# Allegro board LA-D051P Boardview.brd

Outline 214.4 x 122.8 mm; copper layers: TOP, GND1, IN1, VCC, IN2, IN3, GND2, BOTTOM. Coordinates in mm from the lower left corner of the outline.

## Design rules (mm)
constraint set DEFAULT: min track width 0.102
net group CLK_SMB: nets CLK_SMB DAT_SMB
net group DIFFPAIR0: nets A_MIC_CLK A_MIC_DATA
net group DIFFPAIR3: nets CLK_CPU_ITP CLK_CPU_ITP#
net group DIFFPAIR35: nets ICSP_CLK ICSP_DAT
net group DIFFPAIR36: nets MSCLK MSDATA
net group DIFFPAIR48: nets PEX_PLL_CLK_OUT PEX_PLL_CLK_OUT#
net group DIFFPAIR84: nets USB3_CTX_C_DRX_N3 USB3_CTX_C_DRX_P3
net group DIFFPAIR96: nets VCC_GT_SENSE VSS_GT_SENSE
net group PECI: nets PECI_EC PECI_MEC1404
net group SVID: nets VIDALERT_N VIDSOUT
net group W12S12: nets PCIE_RCOMPN PCIE_RCOMPP
net group W12S15: nets SD_RCOMP XCLK_BIASREF
net group 15: nets EC_SPI_CLK EC_SPICLK_R EMMC_RCOMP GPU_BUFRST GPU_JTAG_TRST# GPU_THM_SMBCLK H_CPU_SVIDALRT# HDA_BIT_CLK HDA_CODEC_BITCLK HDA_CODEC_RST# HDA_RST# MEC_XTAL2 NVVDD_GND_SENSE NVVDD_SENSE PCH_PLTRST# PCH_RSMRST# PCH_RTCRST# PCH_RTCX1 PCH_RTCX2 PCH_SMBCLK PCH_SPI_CLK PCH_SPI_CLK_R PLT_RST_VGA# PLT_RST_VGA_MON# RTCRST_ON SMBCLK SML0_SMBCLK SRTCRST# SUSACK# TS_RST# USB2_COMP VCCSENSE VIDSCLK VR_SCLK VR_SDA VSA_SEN+ VSA_SEN- VSSSENSE XTAL24_IN XTAL24_OUT
net group ASYNCHRONOUS SIGNALS: nets H_THERMTRIP#
net group CLK: nets H_PROCHOT#
net group CPU: nets H_CATERR# H_PROCHOT#_R XDP_OBS0_R XDP_OBS1_R
net group CRITICAL: nets H_CPUPWRGD INTRUDER# PCH_DPWROK SYS_PWROK
net group DDR-DQS: nets DDR_A_DQS0 DDR_A_DQS1 DDR_A_DQS2 DDR_A_DQS3 DDR_A_DQS4 DDR_A_DQS5 DDR_A_DQS6 DDR_A_DQS7 DDR_A_DQS#0 DDR_A_DQS#1 DDR_A_DQS#2 DDR_A_DQS#3 DDR_A_DQS#4 DDR_A_DQS#5 DDR_A_DQS#6 DDR_A_DQS#7 DDR_B_DQS0 DDR_B_DQS1 DDR_B_DQS2 DDR_B_DQS3 DDR_B_DQS4 DDR_B_DQS5 DDR_B_DQS6 DDR_B_DQS7 DDR_B_DQS#0 DDR_B_DQS#1 DDR_B_DQS#2 DDR_B_DQS#3 DDR_B_DQS#4 DDR_B_DQS#5 DDR_B_DQS#6 DDR_B_DQS#7
net group DDR-RST: nets DDR_DRAMRST#
net group DDRA-CLK: nets DDR_A_CLK0 DDR_A_CLK1 DDR_A_CLK#0 DDR_A_CLK#1
net group DDRA-CMD: nets DDR_A_BS0 DDR_A_BS1 DDR_A_BS2 DDR_A_CAS# DDR_A_MA0 DDR_A_MA1 DDR_A_MA2 DDR_A_MA3 DDR_A_MA4 DDR_A_MA5 DDR_A_MA6 DDR_A_MA7 DDR_A_MA8 DDR_A_MA9 DDR_A_MA10 DDR_A_MA11 DDR_A_MA12 DDR_A_MA13 DDR_A_MA14 DDR_A_MA15 DDR_A_RAS# DDR_A_WE#
net group DDRA-CTL: nets DDR_A_CKE0 DDR_A_CKE1 DDR_A_CS#0 DDR_A_CS#1 DDR_A_ODT0 DDR_A_ODT1
net group DDRA-D0: nets DDR_A_D0 DDR_A_D1 DDR_A_D2 DDR_A_D3 DDR_A_D4 DDR_A_D5 DDR_A_D6 DDR_A_D7
net group DDRA-D1: nets DDR_A_D8 DDR_A_D9 DDR_A_D10 DDR_A_D11 DDR_A_D12 DDR_A_D13 DDR_A_D14 DDR_A_D15
net group DDRA-D2: nets DDR_A_D16 DDR_A_D17 DDR_A_D18 DDR_A_D19 DDR_A_D20 DDR_A_D21 DDR_A_D22 DDR_A_D23
net group DDRA-D3: nets DDR_A_D24 DDR_A_D25 DDR_A_D26 DDR_A_D27 DDR_A_D28 DDR_A_D29 DDR_A_D30 DDR_A_D31
net group DDRA-D4: nets DDR_A_D32 DDR_A_D33 DDR_A_D34 DDR_A_D35 DDR_A_D36 DDR_A_D37 DDR_A_D38 DDR_A_D39
net group DDRA-D5: nets DDR_A_D40 DDR_A_D41 DDR_A_D42 DDR_A_D43 DDR_A_D44 DDR_A_D45 DDR_A_D46 DDR_A_D47
net group DDRA-D6: nets DDR_A_D48 DDR_A_D49 DDR_A_D50 DDR_A_D51 DDR_A_D52 DDR_A_D53 DDR_A_D54 DDR_A_D55
net group DDRA-D7: nets DDR_A_D56 DDR_A_D57 DDR_A_D58 DDR_A_D59 DDR_A_D60 DDR_A_D61 DDR_A_D62 DDR_A_D63
net group DDRB-CLK: nets DDR_B_CLK0 DDR_B_CLK1 DDR_B_CLK#0 DDR_B_CLK#1
net group DDRB-CMD: nets DDR_B_BS0 DDR_B_BS1 DDR_B_BS2 DDR_B_CAS# DDR_B_MA0 DDR_B_MA1 DDR_B_MA2 DDR_B_MA3 DDR_B_MA4 DDR_B_MA5 DDR_B_MA6 DDR_B_MA7 DDR_B_MA8 DDR_B_MA9 DDR_B_MA10 DDR_B_MA11 DDR_B_MA12 DDR_B_MA13 DDR_B_MA14 DDR_B_MA15 DDR_B_RAS# DDR_B_WE#
net group DDRB-CTL: nets DDR_B_CKE0 DDR_B_CKE1 DDR_B_CS#0 DDR_B_CS#1 DDR_B_ODT0 DDR_B_ODT1
net group DDRB-D0: nets DDR_B_D0 DDR_B_D1 DDR_B_D2 DDR_B_D3 DDR_B_D4 DDR_B_D5 DDR_B_D6 DDR_B_D7
net group DDRB-D1: nets DDR_B_D8 DDR_B_D9 DDR_B_D10 DDR_B_D11 DDR_B_D12 DDR_B_D13 DDR_B_D14 DDR_B_D15
net group DDRB-D2: nets DDR_B_D16 DDR_B_D17 DDR_B_D18 DDR_B_D19 DDR_B_D20 DDR_B_D21 DDR_B_D22 DDR_B_D23
net group DDRB-D3: nets DDR_B_D24 DDR_B_D25 DDR_B_D26 DDR_B_D27 DDR_B_D28 DDR_B_D29 DDR_B_D30 DDR_B_D31
net group DDRB-D4: nets DDR_B_D32 DDR_B_D33 DDR_B_D34 DDR_B_D35 DDR_B_D36 DDR_B_D37 DDR_B_D38 DDR_B_D39
net group DDRB-D5: nets DDR_B_D40 DDR_B_D41 DDR_B_D42 DDR_B_D43 DDR_B_D44 DDR_B_D45 DDR_B_D46 DDR_B_D47
net group DDRB-D6: nets DDR_B_D48 DDR_B_D49 DDR_B_D50 DDR_B_D51 DDR_B_D52 DDR_B_D53 DDR_B_D54 DDR_B_D55
net group DDRB-D7: nets DDR_B_D56 DDR_B_D57 DDR_B_D58 DDR_B_D59 DDR_B_D60 DDR_B_D61 DDR_B_D62 DDR_B_D63
net group EDP: nets EDP_AUX#_C EDP_AUX_C EDP_AUX_DN EDP_AUX_DP EDP_TX0#_C EDP_TX0_C EDP_TX0_DN EDP_TX0_DP EDP_TX1#_C EDP_TX1_C EDP_TX1_DN EDP_TX1_DP
net group FBA-CLK: nets FB_A_CLK0 FB_A_CLK1 FB_A_CLK#0 FB_A_CLK#1
net group FBA-CMD: nets FB_A_CMD0 FB_A_CMD1 FB_A_CMD2 FB_A_CMD3 FB_A_CMD4 FB_A_CMD5 FB_A_CMD6 FB_A_CMD7 FB_A_CMD8 FB_A_CMD9 FB_A_CMD10 FB_A_CMD11 FB_A_CMD12 FB_A_CMD13 FB_A_CMD14 FB_A_CMD15 FB_A_CMD16 FB_A_CMD17 FB_A_CMD18 FB_A_CMD19 FB_A_CMD20 FB_A_CMD21 FB_A_CMD22 FB_A_CMD23 FB_A_CMD24 FB_A_CMD25 FB_A_CMD26 FB_A_CMD27 FB_A_CMD28 FB_A_CMD29 FB_A_CMD30
net group FBA-D0: nets FB_A_D0 FB_A_D1 FB_A_D2 FB_A_D3 FB_A_D4 FB_A_D5 FB_A_D6 FB_A_D7 FB_A_DQM0
net group FBA-D1: nets FB_A_D8 FB_A_D9 FB_A_D10 FB_A_D11 FB_A_D12 FB_A_D13 FB_A_D14 FB_A_D15 FB_A_DQM1
net group FBA-D2: nets FB_A_D16 FB_A_D17 FB_A_D18 FB_A_D19 FB_A_D20 FB_A_D21 FB_A_D22 FB_A_D23 FB_A_DQM2
net group FBA-D3: nets FB_A_D24 FB_A_D25 FB_A_D26 FB_A_D27 FB_A_D28 FB_A_D29 FB_A_D30 FB_A_D31 FB_A_DQM3
net group FBA-D4: nets FB_A_D32 FB_A_D33 FB_A_D34 FB_A_D35 FB_A_D36 FB_A_D37 FB_A_D38 FB_A_D39 FB_A_DQM4
net group FBA-D5: nets FB_A_D40 FB_A_D41 FB_A_D42 FB_A_D43 FB_A_D44 FB_A_D45 FB_A_D46 FB_A_D47 FB_A_DQM5
net group FBA-D6: nets FB_A_D48 FB_A_D49 FB_A_D50 FB_A_D51 FB_A_D52 FB_A_D53 FB_A_D54 FB_A_D55 FB_A_DQM6
net group FBA-D7: nets FB_A_D56 FB_A_D57 FB_A_D58 FB_A_D59 FB_A_D60 FB_A_D61 FB_A_D62 FB_A_D63 FB_A_DQM7
net group FBA-DQS: nets FB_A_DQS0 FB_A_DQS1 FB_A_DQS2 FB_A_DQS3 FB_A_DQS4 FB_A_DQS5 FB_A_DQS6 FB_A_DQS7 FB_A_DQS#0 FB_A_DQS#1 FB_A_DQS#2 FB_A_DQS#3 FB_A_DQS#4 FB_A_DQS#5 FB_A_DQS#6 FB_A_DQS#7
net group HDA: nets HDA_CODEC_SDIN0 HDA_CODEC_SDOUT HDA_CODEC_SYNC HDA_SDIN0 HDA_SDOUT HDA_SYNC
net group HDMI: nets CPU_DPB_CTRLCLK_R CPU_DPB_CTRLDAT_R HDMI_CLK HDMI_CLK# HDMI_DATA0 HDMI_DATA0# HDMI_DATA1 HDMI_DATA1# HDMI_DATA2 HDMI_DATA2# PCH_HDMI_CLK PCH_HDMI_DATA TMDS_L_TX0N TMDS_L_TX0P TMDS_L_TX1N TMDS_L_TX1P TMDS_L_TX2N TMDS_L_TX2P TMDS_L_TXCN TMDS_L_TXCP TMDS_TX0N TMDS_TX0P TMDS_TX1N TMDS_TX1P TMDS_TX2N TMDS_TX2P TMDS_TXCN TMDS_TXCP
net group HP: nets AUD_HP_OUT_L_CN AUD_HP_OUT_R_CN LINE-IN-L LINE-IN-R
net group I2C: nets I2C_SCL_TP I2C_SCL_TP_R I2C_SDA_TP I2C_SDA_TP_R I2CA_SCL I2CA_SDA I2CB_SCL I2CB_SDA I2CC_SCL I2CC_SDA I2CS_SCL I2CS_SDA
net group MDI: nets MDI0+ MDI0- MDI1+ MDI1- MDO0+ MDO0- MDO1+ MDO1-
net group PCIE: nets PCIE_PRX_LANTX_N3_C PCIE_PRX_LANTX_N6 PCIE_PRX_LANTX_P3_C PCIE_PRX_LANTX_P6 PCIE_PRX_WLANTX_N5 PCIE_PRX_WLANTX_P5 PCIE_PTX_LANRX_N6 PCIE_PTX_LANRX_N6_C PCIE_PTX_LANRX_P6 PCIE_PTX_LANRX_P6_C PCIE_PTX_WLANRX_N5 PCIE_PTX_WLANRX_N5_C PCIE_PTX_WLANRX_P5 PCIE_PTX_WLANRX_P5_C
net group PEG-RX_15_20/15/20/20/20: nets PCIE_CRX_C_GTX_N1 PCIE_CRX_C_GTX_N2 PCIE_CRX_C_GTX_N3 PCIE_CRX_C_GTX_N4 PCIE_CRX_C_GTX_P1 PCIE_CRX_C_GTX_P2 PCIE_CRX_C_GTX_P3 PCIE_CRX_C_GTX_P4 PCIE_CRX_GTX_N1 PCIE_CRX_GTX_N2 PCIE_CRX_GTX_N3 PCIE_CRX_GTX_N4 PCIE_CRX_GTX_P1 PCIE_CRX_GTX_P2 PCIE_CRX_GTX_P3 PCIE_CRX_GTX_P4
net group PEG-TX_15_20/15/20/20/20: nets PCIE_CTX_C_GRX_N1 PCIE_CTX_C_GRX_N2 PCIE_CTX_C_GRX_N3 PCIE_CTX_C_GRX_N4 PCIE_CTX_C_GRX_P1 PCIE_CTX_C_GRX_P2 PCIE_CTX_C_GRX_P3 PCIE_CTX_C_GRX_P4 PCIE_CTX_GRX_N1 PCIE_CTX_GRX_N2 PCIE_CTX_GRX_N3 PCIE_CTX_GRX_N4 PCIE_CTX_GRX_P1 PCIE_CTX_GRX_P2 PCIE_CTX_GRX_P3 PCIE_CTX_GRX_P4
net group PLATFORM CLK: nets CLK_PCIE_LAN_N2 CLK_PCIE_LAN_P2 CLK_PCIE_WLAN_N1 CLK_PCIE_WLAN_P1 CLK_PEG_VGA CLK_PEG_VGA#
net group POWER: nets +0.675VS_VREF_CA0 +0.675VS_VREF_CA1 +0.675VS_VREF_DQ0 +0.675VS_VREF_DQ1 +0.675VS_VTT +0.675VSP +1.0V_APLL +1.0V_CLK4_F100OC +1.0V_CLK5 +1.0V_CLK6_24TBT +1.0V_DTS +1.0V_MPHYJP +1.0V_MPHYPLL +1.0V_PRIM_D +1.0V_PRIM_JP +1.0V_VCCSFR +1.0V_VCCST +1.0V_VCCSTU +1.0V_XDP +1.0VO_DSW +1.0VS_DGPU +1.0VS_PLLAVDD +1.0VS_VCCSTG +1.0VS_VCCSTG_IO +1.8V_PRIM +1.8V_PRIM_VS +1.8VALWP +1.8VS +1.8VS_3VS_PGPPA +1.35V_VCCSFR_OC +1.35V_VDDQ +1.35V_VDDQC +1.35VP +1.35VS_VRAM +1VALWP +3V_1.8V_PGPPA +3V_PGPPB +3V_PGPPC +3V_PGPPE +3V_PRIM +3V_PRIM_RTC +3V_PRIMJP +3V_SPI +3VALW_DSW +3VALW_EC +3VALWP +3VL_RTC +3VLP +3VS_CAM +3VS_D +3VS_DGPU +3VS_DGPU_AON +3VS_TOUCH +5V_CAM +5V_HDD +5V_PVDD +5V_USB_PWR1 +5V_USB_PWR2 +5V_USB_PWR3 +5VA +5VALWP +5VS_KBL +17.4V_BATT+ +17.4V_BATT++ +19V_ADPIN +19V_VIN +19VB_1.35V +19VB_+1VALWP +19VB_VGA +A_VCC +CODEC_AVDD2 +FAN_POWER +LAN_REGOUT +LAN_VDD10 +LAN_VDD33 +LAN_VDDREG +LCDVDD +LCDVDD_CONN +MIC2-VREFO +RTCBATT +V_TS +VDD_TOUCH +VDISPLAY_VCC
net group REF-GND: nets ALL_SYS_PWRGD BLUETOOTH_EN BST1_VGA BST1_VGA_R BST2_VGA BST2_VGA_R BST_1.35V BST_1.35V_R BST_3V BST_5V CFG0 CFG1 CFG2 CFG3 CFG4 CFG5 CFG6 CFG7 CFG8 CFG9 CFG10 CFG11 CFG12 CFG13 CFG14 CFG15 CFG16 CFG17 CFG18 CFG19 CLK_PCI_LPC_MEC CPU_XDP_TCK0 LG1_VGA LG2_VGA LG_1.35V LGATE_CHG LPC_LAD0 LPC_LAD1 LPC_LAD2 LPC_LAD3 LX1_VGA LX2_VGA LX_1.8VALW LX_1.35V LX_3V LX_5V MIC_CLK_C MPHYP_PWR_EN PCH_RSMRST#_Q PCI_CLK_LPC1 PHASE_CHG POK RESET_OUT# RUNPWROK SIO_PWRBTN# SIO_PWRBTN#_R SOC_XDP_TDI SOC_XDP_TDO SOC_XDP_TMS SOC_XDP_TRST# SYS_RESET# UG2_VGA UG_1.35V UGATE_CHG USB3_CM_P0 USB3_DE1_P0 USB3_DE2_P0 USB3_EQ1_P0 USB3_EQ2_P0 USB3_ERD_P0 USB3_OS1_P0 USB3_OS2_P0 USB3_P0_PIN6 USB3_P0_PIN18 VCCST_PWRGD XDP_OBS2_R XDP_OBS3_R XDP_PRDY# XDP_PREQ# XTALIN XTLI XTLO
net group SATA: nets SATA3_PRX_HDDTX_N0 SATA3_PRX_HDDTX_P0 SATA3_PTX_HDDRX_N0 SATA3_PTX_HDDRX_P0 SATA_PRX_DTX_N0 SATA_PRX_DTX_N0_R SATA_PRX_DTX_N0_RC SATA_PRX_DTX_P0 SATA_PRX_DTX_P0_R SATA_PRX_DTX_P0_RC SATA_PTX_DRX_N0 SATA_PTX_DRX_N0_R SATA_PTX_DRX_N0_RC SATA_PTX_DRX_P0 SATA_PTX_DRX_P0_R SATA_PTX_DRX_P0_RC
net group SMBUS: nets GPU_THM_SMBDAT PBAT_CHG_SMBCLK PBAT_CHG_SMBDAT PCH_SMBDAT SMBDATA SML0_SMBDATA THM_SML1_CLK THM_SML1_DATA
net group SPI: nets EC_MISO_R EC_MOSI_R EC_SPI_CS0# EC_SPI_MISO EC_SPI_MOSI EC_SPICS#_R PCH_SPI_D0 PCH_SPI_D0_R PCH_SPI_D1 PCH_SPI_D1_R PCH_SPI_D2 PCH_SPI_D2_R PCH_SPI_D3 PCH_SPI_D3_R
net group THMEL: nets REMOTE1+ REMOTE1- REMOTE2+ REMOTE2-
net group USB20: nets USB20_CR_N6_R USB20_CR_P6_R USB20_JUSB1_N0_R USB20_JUSB1_P0_R USB20_JUSB2_N1_R USB20_JUSB2_P1_R USB20_JUSB3_N4_R USB20_JUSB3_P4_R USB20_N1 USB20_N2 USB20_N4 USB20_N5 USB20_N5_L USB20_N6 USB20_N7 USB20_N8 USB20_P1 USB20_P2 USB20_P4 USB20_P5 USB20_P5_L USB20_P6 USB20_P7 USB20_P8
net group USB30: nets USB3_CRX_C_RD_DTX_N3 USB3_CRX_C_RD_DTX_P3 USB3_CRX_DTX_N1 USB3_CRX_DTX_N2 USB3_CRX_DTX_N3 USB3_CRX_DTX_P1 USB3_CRX_DTX_P2 USB3_CRX_DTX_P3 USB3_CRX_L_DTX_N3 USB3_CRX_L_DTX_P3 USB3_CRX_RD_DTX_N3 USB3_CRX_RD_DTX_P3 USB3_CTX_C_RD_DRX_N3 USB3_CTX_C_RD_DRX_P3 USB3_CTX_DRX_N1 USB3_CTX_DRX_N2 USB3_CTX_DRX_N3 USB3_CTX_DRX_P1 USB3_CTX_DRX_P2 USB3_CTX_DRX_P3 USB3_CTX_L_DRX_N3 USB3_CTX_L_DRX_P3 USB3_CTX_RD_DRX_N3 USB3_CTX_RD_DRX_P3 USB3RN1_JUSB1_R USB3RN2_JUSB2_R USB3RP1_JUSB1_R USB3RP2_JUSB2_R USB3TN1_JUSB1_C USB3TN1_JUSB1_R USB3TN2_JUSB2_C USB3TN2_JUSB2_R USB3TP1_JUSB1_C USB3TP1_JUSB1_R USB3TP2_JUSB2_C USB3TP2_JUSB2_R
net group W5S25: nets EDP_COMP
net group W10S20: nets +0.675V_DDR_VREFCA +0.675V_DDRA_VREFCA +0.675V_DDRA_VREFDQ +0.675V_DDRB_VREFCA +0.675V_DDRB_VREFDQ HPOUT-L HPOUT-R MIC1-L
net group W12S20: nets CFG_RCOMP CPU_POPIRCOMP CSI2_COMP EDRAM_OPIO_RCOMP EOPIO_RCOMP PCH_OPIRCOMP
net group W12S25: nets SM_RCOMP0 SM_RCOMP1 SM_RCOMP2
net group W20S20: nets +0.675V_A_VREFDQ +0.675V_B_VREFDQ +0.675V_VREFCA
net group W40S10: nets MIC_IN_R RING2 RING2_R
net group W40S20: nets INT-SPK-L+ INT-SPK-L- INT-SPK-R+ INT-SPK-R- SPK_L1-_CONN SPK_L2+_CONN SPK_R1-_CONN SPK_R2+_CONN
nets with their own width: min track width 0.254; nets +1.8V_PG
nets with their own width: min track width 0.508; nets +3VALW +3VL_RTC_VBAT +3VS +5VALW +5VS GND
nets with their own width: min track width 2.032; nets +3VS_WLAN_NGFF

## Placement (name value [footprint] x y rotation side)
C94  1U_0402_6.3V6K  [C_0402]  15.28 66.41 0 top
C2305  10U_0603_6.3V6M  [C_0603]  169.6 10.79 270 top
C2306  10U_0603_6.3V6M  [C_0603]  168.33 10.79 270 top
C2307  10U_0805_10V4Z  [C_0805]  164.36 17.96 180 top
C2308  10U_0603_6.3V6M  [C_0603]  164.2 16.44 180 top
C2309  0.01U_0603_25V7K  [C_0603]  170.87 11.29 270 top
C2316  10U_0603_6.3V6M  [C_0603]  174.62 12.25 0 top
C2318  10U_0603_6.3V6M  [C_0603]  174.62 13.52 0 top
C2322  0.01U_0603_25V7K  [C_0603]  173.41 11.29 270 top
C2323  10U_0603_6.3V6M  [C_0603]  176.84 17.14 270 top
C2324  10U_0603_6.3V6M  [C_0603]  175.63 17.14 270 top
C2498  0.1U_0402_10V6K  [C_0402]  155.25 6.6 270 top
C2500  2200P_0402_25V7K  [C_0402]  95.17 35.81 0 bottom
C2502  2200P_0402_25V7K  [C_0402]  156.14 6.6 0 top
C2504  2200P_0402_25V7K  [C_0402]  157.92 6.6 0 top
C2505  2200P_0402_25V7K  [C_0402]  159.63 86.02 90 bottom
C4311  0.1U_0402_16V7K  [C_0402]  4.04 98.91 0 top
C4312  0.1U_0402_16V7K  [C_0402]  4.04 99.8 0 top
C4313  0.1U_0402_16V7K  [C_0402]  4.04 97.13 0 top
C4314  0.1U_0402_16V7K  [C_0402]  4.04 98.02 0 top
C4321  0.1U_0402_16V7K  [C_0402]  4.06 96.24 0 top
C4322  0.1U_0402_16V7K  [C_0402]  4.06 95.36 0 top
C5216  1000P_0402_50V7K  [C_0402]  168.84 17.38 90 bottom
C5217  1000P_0402_50V7K  [C_0402]  169.73 17.38 90 bottom
C5220  2200P_0402_25V7K  [C_0402]  18.97 67.43 0 top
C5221  0.1U_0402_10V6K  [C_0402]  15.8 62.17 270 top
C5222  10P_0402_50V8J  [C_0402]  168.33 13.57 90 top
C5223  10P_0402_50V8J  [C_0402]  164.15 15.36 180 top
C5224  10P_0402_50V8J  [C_0402]  173.6 14.58 90 top
C5225  10P_0402_50V8J  [C_0402]  174.55 16.51 270 top
C5230  0.1U_0402_10V7K  [C_0402]  119.44 2.61 270 top
C5231  1U_0603_16V7  [C_0603]  149.03 12.75 0 top
C5232  10P_0402_50V8J  [C_0402]  148.33 1.5 90 top
C5233  10P_0402_50V8J  [C_0402]  151.36 3.74 0 top
CA21  22P_0402_50V8J  [C_0402]  196.96 12.82 0 bottom
CA22  22P_0402_50V8J  [C_0402]  4.68 82.1 0 top
CA23  2.2U_0603_6.3V6K  [C_0603]  195.26 25.65 270 bottom
CA24  1U_0402_6.3V6K  [C_0402]  199.52 22.53 180 top
CA25  1U_0402_6.3V6K  [C_0402]  199.51 24.77 270 bottom
CA26  22P_0402_50V8J  [C_0402]  141.8 68.83 180 top
CA29  1000P_0402_50V7K  [C_0402]  203.33 16.44 180 top
CA30  1000P_0402_50V7K  [C_0402]  205.47 16.56 0 top
CA31  1000P_0402_50V7K  [C_0402]  208.16 16.56 180 top
CA32  1000P_0402_50V7K  [C_0402]  210.55 16.44 0 top
CA33  100P_0402_50V8J  [C_0402]  193.48 27.82 270 bottom
CA38  1000P_0402_50V7K  [C_0402]  193.48 33 90 bottom
CA39  100P_0402_50V8J  [C_0402]  193.48 28.93 90 bottom
CA40  1000P_0402_50V7K  [C_0402]  193.48 31.75 270 bottom
CA51  0.1U_0402_16V7K  [C_0402]  194.22 24.09 90 top
CA53  4.7U_0603_6.3V6K  [C_0603]  199.38 18.22 180 top
CA54  0.1U_0402_16V7K  [C_0402]  201.22 16.13 270 top
CA55  4.7U_0603_6.3V6K  [C_0603]  199.38 16.95 180 top
CA56  0.1U_0402_16V7K  [C_0402]  199.02 15.8 180 top
CA57  4.7U_0603_6.3V6K  [C_0603]  199.7 14.6 270 top
CA58  0.1U_0402_16V7K  [C_0402]  198.56 14.1 270 top
CA59  4.7U_0603_6.3V6K  [C_0603]  194.75 16.25 90 top
CA60  0.1U_0402_16V7K  [C_0402]  195.76 14.61 270 top
CA61  4.7U_0603_6.3V6K  [C_0603]  202.43 22.79 0 bottom
CA62  10U_0603_6.3V6M  [C_0603]  192.78 24.44 0 bottom
CA63  10U_0603_6.3V6M  [C_0603]  203.83 24.18 180 bottom
CA64  10U_0603_6.3V6M  [C_0603]  196.02 17.64 270 top
CA65  0.1U_0402_16V7K  [C_0402]  194.19 12.88 180 top
CA67  4.7U_0603_6.3V6K  [C_0603]  191.38 24.44 180 bottom
CA68  4.7U_0603_6.3V6K  [C_0603]  191.51 23.17 180 bottom
CA69  100P_0402_50V8J  [C_0402]  191.45 13.82 90 top
CA71  4.7U_0603_6.3V6K  [C_0603]  193.17 23.87 90 top
CA74  10U_0603_6.3V6M  [C_0603]  191.38 19.54 180 bottom
CC8  0.1U_0201_10V6K  [C_0201]  180.4 20.27 90 top
CC9  10P_0402_50V8J  [C_0402]  181.22 21.28 270 top
CC10  1U_0402_6.3V6K  [C_0402]  145.08 74.41 0 top
CC11  1U_0402_6.3V6K  [C_0402]  149.17 74.41 180 top
CC12  18P_0402_50V8J  [C_0402]  134.2 106.77 0 bottom
CC13  15P_0402_50V8J  [C_0402]  131.56 106.77 180 bottom
CC14  0.1U_0201_10V6K  [C_0201]  162.72 60.82 180 top
CC15  5.6P_0402_50V8J  [C_0402]  155.25 84.93 270 bottom
CC16  5.6P_0402_50V8J  [C_0402]  155.57 85.77 90 bottom
CC17  0.22U_0402_16V7K  [C_0402]  146.73 108.11 270 bottom
CC18  0.22U_0402_16V7K  [C_0402]  148.63 108.11 270 bottom
CC19  0.22U_0402_16V7K  [C_0402]  147.62 108.11 270 bottom
CC20  0.22U_0402_16V7K  [C_0402]  143.81 108.11 270 bottom
CC21  0.22U_0402_16V7K  [C_0402]  145.71 108.11 270 bottom
CC22  0.22U_0402_16V7K  [C_0402]  144.82 108.11 270 bottom
CC23  0.22U_0402_16V7K  [C_0402]  139.49 108.11 270 bottom
CC24  0.22U_0402_16V7K  [C_0402]  140.5 108.11 270 bottom
CC25  0.1U_0402_10V7K  [C_0402]  141.9 108.11 270 bottom
CC26  0.1U_0402_10V7K  [C_0402]  142.92 108.11 270 bottom
CC27  10U_0402_6.3V6M  [C_0402]  123.63 86.66 90 top
CC28  10U_0402_6.3V6M  [C_0402]  124.58 86.66 90 top
CC29  1U_0201_6.3V6K  [C_0201]  134.88 86.65 135 top
CC30  1U_0201_6.3V6K  [C_0201]  135.1 88.26 180 top
CC31  1U_0201_6.3V6K  [C_0201]  127.67 86.48 180 top
CC32  1U_0201_6.3V6K  [C_0201]  135.34 87.18 0 top
CC33  1U_0402_6.3V6K  [C_0402]  120.91 86.67 180 top
CC34  1U_0402_6.3V6K  [C_0402]  121.79 86.66 90 top
CC35  1U_0402_6.3V6K  [C_0402]  122.74 86.66 90 top
CC36  1U_0402_6.3V6K  [C_0402]  135.13 89.02 180 top
CC37  10U_0603_6.3V6M  [C_0603]  134.74 69.33 180 top
CC38  10U_0603_6.3V6M  [C_0603]  134.74 68.06 180 top
CC39  10U_0603_6.3V6M  [C_0603]  123.5 68.19 180 top
CC40  10U_0603_6.3V6M  [C_0603]  128.77 70.73 180 top
CC41  10U_0603_6.3V6M  [C_0603]  128.77 68.19 180 top
CC42  10U_0603_6.3V6M  [C_0603]  128.77 69.46 180 top
CC43  1U_0402_6.3V6K  [C_0402]  135.44 73.38 90 top
CC44  1U_0201_6.3V6K  [C_0201]  123.31 73.87 90 top
CC45  1U_0402_6.3V6K  [C_0402]  129.91 73.38 90 top
CC46  1U_0402_6.3V6K  [C_0402]  125.79 74.43 270 top
CC47  1U_0402_6.3V6K  [C_0402]  128 88 0 top
CC48  1U_0402_6.3V6K  [C_0402]  142.74 102.18 270 top
CC49  0.1U_0201_10V6K  [C_0201]  138.69 86.7 0 top
CC50  1U_0402_6.3V6K  [C_0402]  175.08 99.5 180 top
CC51  4.7U_0603_6.3V6K  [C_0603]  171.7 99.5 0 top
CC52  0.1U_0402_25V6  [C_0402]  187.32 74.93 270 top
CC55  1U_0402_6.3V6K  [C_0402]  139.95 95.63 225 top
CC56  1U_0201_6.3V6K  [C_0201]  138.84 100.83 180 top
CC57  0.1U_0201_10V6K  [C_0201]  157.94 61.08 0 top
CC58  0.1U_0402_25V6  [C_0402]  183.05 83.11 0 top
CC59  1U_0402_6.3V6K  [C_0402]  186.43 74.93 270 top
CC61  1U_0402_6.3V6K  [C_0402]  143.93 96.56 180 top
CC63  10P_0402_50V8J  [C_0402]  140.47 85.97 180 top
CC64  0.1U_0402_10V7K  [C_0402]  156.06 99.37 0 top
CC67  1U_0402_6.3V6K  [C_0402]  140.39 92.65 270 top
CC68  1U_0201_6.3V6K  [C_0201]  144.1 95.56 0 top
CC71  0.1U_0402_10V7K  [C_0402]  158.49 70.17 270 top
CC72  1U_0402_6.3V6K  [C_0402]  143.83 90.73 180 top
CC73  1U_0402_6.3V6K  [C_0402]  142.98 92.3 90 top
CC74  1U_0402_6.3V6K  [C_0402]  143.87 92.57 0 top
CC75  1U_0402_6.3V6K  [C_0402]  143.63 102.18 270 top
CC76  1U_0402_6.3V6K  [C_0402]  141.67 88.63 270 top
CC77  1U_0402_6.3V6K  [C_0402]  148.58 87.67 90 top
CC78  0.1U_0201_10V6K  [C_0201]  147.11 87.3 90 top
CC79  0.1U_0201_10V6K  [C_0201]  141.18 85.63 270 top
CC80  1U_0201_6.3V6K  [C_0201]  142.85 94.5 270 top
CC81  22U_0603_6.3V6M  [C_0603]  143.6 94.23 0 top
CC82  22U_0603_6.3V6M  [C_0603]  175.06 85.4 90 top
CC83  0.1U_0201_10V6K  [C_0201]  110.38 109.53 0 bottom
CC84  1U_0402_6.3V6K  [C_0402]  141.65 86.73 0 top
CC85  1U_0402_6.3V6K  [C_0402]  152.09 85.97 180 top
CC86  1U_0402_6.3V6K  [C_0402]  146.93 102.29 270 top
CC87  1U_0402_6.3V6K  [C_0402]  149.03 96.97 270 top
CC88  0.1U_0402_25V6  [C_0402]  169.4 46.09 0 top
CC89  0.1U_0402_25V6  [C_0402]  166.22 41.33 0 top
CC90  0.1U_0402_25V6  [C_0402]  162.44 50.16 180 top
CC91  1U_0402_6.3V6K  [C_0402]  142.14 91.88 180 top
CC92  0.1U_0201_10V6K  [C_0201]  125.88 20.57 0 top
CC93  2.2U_0402_6.3V6M  [C_0402]  129.53 23.25 270 top
CC94  1000P_0402_50V7K  [C_0402]  178.75 79.61 90 top
CC95  10P_0402_50V8J  [C_0402]  177.86 79.61 90 top
CC96  0.1U_0402_25V6  [C_0402]  176.97 79.61 90 top
CC97  1U_0402_6.3V6K  [C_0402]  175.95 75.73 90 top
CC98  1U_0402_6.3V6K  [C_0402]  177.73 73.66 270 top
CC99  1U_0402_6.3V6K  [C_0402]  180.59 75.16 90 top
CC100  0.1U_0402_25V6  [C_0402]  180.59 77.86 270 top
CC101  0.1U_0402_25V6  [C_0402]  169.16 48.65 270 top
CC102  1U_0402_6.3V6K  [C_0402]  144.14 88.99 180 top
CC103  1U_0402_6.3V6K  [C_0402]  146.18 91.3 135 top
CC104  1U_0402_6.3V6K  [C_0402]  159.81 65.7 270 top
CC111  22U_0603_6.3V6M  [C_0603]  141.79 90.73 180 top
CC112  22U_0603_6.3V6M  [C_0603]  141.66 94.25 180 top
CC113  22U_0603_6.3V6M  [C_0603]  136.9 91.34 270 top
CC114  22U_0603_6.3V6M  [C_0603]  138.11 91.34 270 top
CC115  22U_0603_6.3V6M  [C_0603]  139.31 91.34 270 top
CC116  22U_0603_6.3V6M  [C_0603]  138.55 92.32 90 top
CC117  1U_0402_6.3V6K  [C_0402]  168.71 42.23 270 top
CC118  22U_0603_6.3V6M  [C_0603]  176.27 85.4 90 top
CC119  22U_0603_6.3V6M  [C_0603]  173.86 85.4 90 top
CC122  1U_0402_6.3V6K  [C_0402]  140.43 88.56 270 top
CC123  22U_0603_6.3V6M  [C_0603]  154.79 97.75 180 top
CC124  22U_0603_6.3V6M  [C_0603]  154.79 99.02 180 top
CC125  22U_0603_6.3V6M  [C_0603]  144.58 101.97 0 top
CC126  22U_0603_6.3V6M  [C_0603]  149.28 101.91 180 top
CC127  22U_0603_6.3V6M  [C_0603]  150.98 99.02 0 top
CC128  22U_0603_6.3V6M  [C_0603]  150.98 97.75 0 top
CC129  22U_0603_6.3V6M  [C_0603]  143.76 100.26 180 top
CC130  22U_0603_6.3V6M  [C_0603]  146.49 99.11 0 top
CC135  0.1U_0402_10V7K  [C_0402]  138.6 108.11 270 bottom
CC136  0.1U_0402_10V7K  [C_0402]  137.58 108.11 270 bottom
CC141  10U_0402_6.3V6M  [C_0402]  127.13 87.94 180 top
CC142  1U_0402_6.3V6K  [C_0402]  154.04 67.31 270 top
CD1  2.2U_0402_6.3V6M  [C_0402]  96.83 49.95 90 top
CD2  0.1U_0402_25V6K  [C_0402]  95.94 49.95 90 top
CD3  0.1U_0402_25V6K  [C_0402]  105.96 35.49 0 top
CD4  1U_0402_6.3V6K  [C_0402]  122.42 46.8 270 top
CD5  1U_0402_6.3V6K  [C_0402]  124.14 39.16 90 top
CD6  1U_0402_6.3V6K  [C_0402]  126.61 46.93 270 top
CD7  1U_0402_6.3V6K  [C_0402]  128.64 39.16 90 top
CD8  1U_0402_6.3V6K  [C_0402]  134.99 39.82 270 top
CD9  1U_0402_6.3V6K  [C_0402]  134.36 46.87 270 top
CD10  10U_0603_6.3V6M  [C_0603]  128.77 47.17 270 top
CD11  10U_0603_6.3V6M  [C_0603]  132.07 47.24 270 top
CD12  10U_0603_6.3V6M  [C_0603]  124.45 47.24 270 top
CD13  10U_0603_6.3V6M  [C_0603]  122.23 38.92 90 top
CD14  10U_0603_6.3V6M  [C_0603]  126.29 38.85 90 top
CD15  10U_0603_6.3V6M  [C_0603]  120.58 47.17 270 top
CD16  330U_D3_2.5VY_R6M  [C_D3]  138.53 63.94 0 top
CD17  2.2U_0402_6.3V6M  [C_0402]  135.88 37.51 90 top
CD18  0.1U_0402_25V6K  [C_0402]  137.41 37.51 90 top
CD19  10U_0603_6.3V6M  [C_0603]  132.45 39.25 90 top
CD20  10U_0603_6.3V6M  [C_0603]  130.04 38.92 90 top
CD21  0.022U_0402_16V7K  [C_0402]  98.67 49.95 90 top
CD22  0.1U_0402_25V6K  [C_0402]  160.51 48.12 0 top
CD23  0.1U_0402_25V6K  [C_0402]  160.7 39.93 0 top
CD24  1U_0402_6.3V6K  [C_0402]  160.51 47.17 0 top
CD25  1U_0402_6.3V6K  [C_0402]  160.7 38.98 0 top
CD26  2.2U_0402_6.3V6M  [C_0402]  158.12 48.38 180 top
CD27  0.1U_0402_25V6K  [C_0402]  158.12 47.36 180 top
CD28  2.2U_0402_6.3V6M  [C_0402]  107.8 36.38 0 top
CD29  0.1U_0402_25V6K  [C_0402]  107.8 37.27 0 top
CD30  0.1U_0402_25V6K  [C_0402]  105.96 36.38 0 top
CD31  0.022U_0402_16V7K  [C_0402]  109.65 34.54 0 top
CD32  1U_0402_6.3V6K  [C_0402]  138.11 34.1 270 top
CD33  1U_0402_6.3V6K  [C_0402]  135.57 26.14 90 top
CD34  1U_0402_6.3V6K  [C_0402]  133.53 34.17 270 top
CD35  1U_0402_6.3V6K  [C_0402]  139.06 26.08 90 top
CD36  1U_0402_6.3V6K  [C_0402]  143.63 26.14 90 top
CD37  1U_0402_6.3V6K  [C_0402]  142.8 34.23 270 top
CD38  10U_0603_6.3V6M  [C_0603]  146.49 25.84 90 top
CD39  10U_0603_6.3V6M  [C_0603]  133.53 25.77 90 top
CD40  10U_0603_6.3V6M  [C_0603]  137.41 25.84 90 top
CD41  10U_0603_6.3V6M  [C_0603]  141.92 25.84 90 top
CD42  10U_0603_6.3V6M  [C_0603]  145.09 34.47 270 top
CD43  10U_0603_6.3V6M  [C_0603]  136.39 34.54 270 top
CD44  10U_0603_6.3V6M  [C_0603]  132.14 34.6 270 top
CD45  10U_0603_6.3V6M  [C_0603]  140.52 34.54 270 top
CD46  330U_D3_2.5VY_R6M  [C_D3]  138.53 59.17 0 top
CD47  2.2U_0402_6.3V6M  [C_0402]  148.42 25.81 90 top
CD48  0.1U_0402_25V6K  [C_0402]  149.35 25.82 90 top
CD49  0.022U_0402_16V7K  [C_0402]  152.44 25.82 90 top
CD50  0.1U_0402_25V6K  [C_0402]  172.76 35.17 0 top
CD51  0.1U_0402_25V6K  [C_0402]  171.58 26.09 180 top
CD52  1U_0402_6.3V6K  [C_0402]  171.58 27.04 180 top
CD53  1U_0402_6.3V6K  [C_0402]  172.76 34.28 0 top
CD54  0.1U_0402_25V6K  [C_0402]  170.82 35.55 180 top
CD55  2.2U_0402_6.3V6M  [C_0402]  170.82 36.44 180 top
CE20  0.1U_0402_16V7K  [C_0402]  171.95 121.1 270 bottom
CE22  2.2U_0603_6.3V6K  [C_0603]  5.9 71.49 90 top
CE23  1000P_0402_50V7K  [C_0402]  4.63 71.48 90 top
CE24  0.01U_0402_16V7K  [C_0402]  3.44 74.86 180 top
CE25  2.2U_0603_6.3V6K  [C_0603]  8.25 69.14 0 top
CE26  0.01U_0402_16V7K  [C_0402]  111.83 85.4 180 top
CE56  1U_0603_10V6K  [C_0603]  113.4 23.3 270 top
CE57  10U_0603_6.3V6M  [C_0603]  119.37 21.9 90 top
CE58  1U_0402_6.3V6K~D  [C_0402]  27.31 62.16 180 top
CE61  1U_0402_6.3V6K  [C_0402]  23.12 68.63 180 top
CE62  10U_0603_6.3V6M  [C_0603]  150.11 13.83 90 top
CE63  0.1U_0402_10V7K  [C_0402]  139.71 1.58 180 top
CE64  1000P_0402_50V7K  [C_0402]  139.38 22.74 270 top
CE65  1000P_0402_50V7K  [C_0402]  127.23 12.31 0 top
CE66  0.1U_0402_25V6  [C_0402]  150.16 6.66 0 top
CE67  0.1U_0402_25V6  [C_0402]  149.03 13.76 90 top
CE68  0.1U_0402_25V6  [C_0402]  128.15 21.2 180 top
CE69  0.1U_0402_25V6  [C_0402]  128.15 20.31 180 top
CE70  0.1U_0402_25V6  [C_0402]  140.26 21.82 90 top
CE71  0.1U_0402_10V7K  [C_0402]  116.58 2.61 270 top
CE72  0.1U_0402_10V7K  [C_0402]  142.12 1.58 180 top
CE73  0.1U_0402_25V6  [C_0402]  136.33 21.82 90 top
CE74  100P_0402_50V8J  [C_0402]  128.09 2.79 180 top
CE75  0.1U_0402_25V6  [C_0402]  128.09 4.25 180 top
CE76  0.1U_0402_10V7K  [C_0402]  134.5 23.68 180 top
CE77  0.047U_0402_16V4Z  [C_0402]  141.22 21.82 90 top
CE78  0.1U_0402_25V6  [C_0402]  134.82 1.58 180 top
CE79  1U_0402_6.3V6K  [C_0402]  152.51 4.82 0 top
CE80  0.1U_0402_25V6  [C_0402]  117.53 2.61 270 top
CE81  0.1U_0402_25V6  [C_0402]  150.11 16.23 90 top
CE82  0.1U_0402_10V7K  [C_0402]  143.5 23.63 270 top
CE83  2200P_0402_25V7K  [C_0402]  124.53 1.71 180 top
CE84  47P_0402_50V8J  [C_0402]  124.59 16.18 180 top
CE85  0.047U_0402_16V4Z  [C_0402]  135.44 21.82 90 top
CE86  220P_0402_50V8J  [C_0402]  142.6 21.77 0 top
CE87  0.1U_0402_10V7K  [C_0402]  128.15 18.47 180 top
CE88  1000P_0402_50V7K  [C_0402]  132.52 22.2 90 top
CE89  100P_0402_50V8J  [C_0402]  149.55 4.63 180 top
CE90  2200P_0402_25V7K  [C_0402]  122.36 2.61 270 top
CE91  680P_0402_50V7K  [C_0402]  21.24 64.27 270 top
CE92  680P_0402_50V7K  [C_0402]  20.31 64.27 270 top
CI1  220U_6.3V_M  [C_MP6VLPS220MC4R2]  195.64 52.51 0 bottom
CI2  0.1U_0402_16V7K  [C_0402]  195.42 57.77 180 bottom
CI3  0.1U_0402_10V7K  [C_0402]  194.29 71.58 90 bottom
CI4  0.1U_0402_10V7K  [C_0402]  193.4 71.58 90 bottom
CI5  0.1U_0402_10V6K  [C_0402]  26.17 83.24 180 top
CI6  4.7U_0805_10V4Z  [C_0805]  188.74 41.58 180 top
CI7  0.1U_0402_16V7K  [C_0402]  191.89 41.79 270 top
CI8  220U_6.3V_M  [C_MP6VLPS220MC4R2]  195.64 37.9 0 bottom
CI9  0.1U_0402_16V7K  [C_0402]  196.78 36.45 270 bottom
CI10  0.1U_0402_10V7K  [C_0402]  190.89 46.61 180 bottom
CI11  0.1U_0402_10V7K  [C_0402]  190.89 45.72 180 bottom
CI12  4.7U_0805_10V4Z  [C_0805]  188.74 44.31 180 top
CI13  0.1U_0402_16V7K  [C_0402]  191.62 50.16 0 top
CI14  0.1U_0402_16V7K  [C_0402]  188.35 47.43 180 top
CI15  0.1U_0402_16V7K  [C_0402]  194.38 50.16 180 top
CI16  0.1U_0402_10V6K  [C_0402]  26.17 82.35 180 top
CI18  47U_0805_6.3V4Z  [C_0805]  188.74 46.09 180 top
CI19  0.1U_0402_10V6K  [C_0402]  26.17 85.02 180 top
CI20  0.1U_0402_10V6K  [C_0402]  20.44 78.66 90 top
CI21  0.1U_0402_10V6K  [C_0402]  17.9 82.43 270 top
CI22  0.1U_0402_10V6K  [C_0402]  26.17 84.13 180 top
CI23  0.01U_0402_16V7K  [C_0402]  25.34 86.99 180 top
CI24  0.1U_0402_10V6K  [C_0402]  17.01 82.43 270 top
CI26  0.1U_0402_16V7K  [C_0402]  192.84 41.79 270 top
CI40  10U_0603_6.3V6M  [C_0603]  195.7 56.7 180 bottom
CI43  10U_0603_6.3V6M  [C_0603]  197.16 39.87 90 bottom
CI44  4.7U_0805_10V4Z  [C_0805]  30.18 42.6 180 bottom
CI45  0.1U_0402_16V7K  [C_0402]  32.11 42.6 0 bottom
CI46  0.1U_0402_16V7K  [C_0402]  32.11 46.73 0 bottom
CI47  0.1U_0402_16V7K  [C_0402]  32.11 45.77 0 bottom
CL3  0.1U_0402_25V6  [C_0402]  172.28 108.2 180 bottom
CL4  4.7U_0603_6.3V6K  [C_0603]  170.94 112.77 90 bottom
CL5  0.1U_0402_25V6  [C_0402]  178.57 102.72 90 top
CL6  0.1U_0402_25V6  [C_0402]  177.68 102.67 180 top
CL7  0.1U_0402_25V6  [C_0402]  175.7 105.8 270 top
CL8  0.1U_0402_25V6  [C_0402]  173.46 104.83 0 top
CL9  1U_0402_6.3V4Z  [C_0402]  173.46 103.94 0 top
CL12  0.1U_0402_16V7K  [C_0402]  177.6 105.29 270 top
CL13  4.7U_0603_6.3V6K  [C_0603]  174.24 100.51 90 top
CL14  10U_0603_6.3V6M  [C_0603]  177.67 101.53 180 top
CL15  0.1U_0402_10V7K  [C_0402]  189.43 94.48 180 bottom
CL16  0.1U_0402_16V7K  [C_0402]  170.68 106.81 270 bottom
CL17  4.7U_0603_6.3V6K  [C_0603]  171.76 105.78 90 bottom
CL19  0.1U_0402_10V7K  [C_0402]  175.32 100.82 90 top
CL30  0.1U_0402_10V7K  [C_0402]  170.73 100.64 0 bottom
CL31  0.1U_0402_10V7K  [C_0402]  170.73 101.53 0 bottom
CL33  100P_1206_2KV8J  [C_1206]  197.92 109.21 90 top
CL36  12P_0402_50V8J  [C_0402]  177.17 107.37 180 bottom
CL37  12P_0402_50V8J  [C_0402]  174.48 107.37 0 bottom
CL39  1U_0402_6.3V6K  [C_0402]  189.05 97.4 180 top
CL41  0.01U_0402_16V7K  [C_0402]  182.7 107.24 180 top
CLRP1  SHORT PADS  [SHORTPADS]  145.54 73.4 90 bottom
CLRP2  SHORT PADS  [SHORTPADS]  148.39 74.41 90 bottom
CLRP3  SHORT PADS  [SHORTPADS]  156.71 106.73 90 bottom
CM4  10U_0603_6.3V6M  [C_0603]  172.78 65.9 270 top
CM5  0.1U_0402_10V7K  [C_0402]  173.92 65.79 270 top
CM6  10U_0603_6.3V6M  [C_0603]  190.56 65.08 180 top
CM7  0.1U_0402_10V7K  [C_0402]  190.32 66.16 180 top
CM8  1U_0402_6.3V6K  [C_0402]  189.4 69.02 0 top
CM9  10P_0402_50V8J  [C_0402]  190.32 68.06 180 top
CM10  10P_0402_50V8J  [C_0402]  190.32 67.11 180 top
CS5  1000P_0402_50V7K  [C_0402]  177.41 7.73 90 bottom
CS6  0.1U_0402_25V6K  [C_0402]  178.3 7.73 90 bottom
CS7  10U_0805_10V6K  [C_0805]  177.79 6.68 270 bottom
CS27  0.1U_0402_25V6K  [C_0402]  180.02 8.26 270 top
CS30  0.01U_0402_16V7K  [C_0402]  180.75 10.34 180 top
CS31  0.01U_0402_16V7K  [C_0402]  180.65 12.25 180 top
CS32  0.01U_0402_16V7K  [C_0402]  180.75 11.23 180 top
CS33  0.01U_0402_16V7K  [C_0402]  189.79 11.87 180 top
CS34  0.01U_0402_16V7K  [C_0402]  180.65 13.14 180 top
CS35  0.01U_0402_16V7K  [C_0402]  189.79 12.75 180 top
CS36  0.01U_0402_16V7K  [C_0402]  189.79 10.98 180 top
CS37  0.01U_0402_16V7K  [C_0402]  189.79 10.09 180 top
CS42  0.01U_0402_16V7K  [C_0402]  179.13 8.26 270 top
CV2  4.7U_0603_6.3V6K  [C_0603]  59.68 67.75 270 top
CV3  4.7U_0603_6.3V6K  [C_0603]  62.54 61.65 270 top
CV4  4.7U_0603_6.3V6K  [C_0603]  73.72 65.78 270 top
CV5  4.7U_0603_6.3V6K  [C_0603]  76.19 65.78 270 top
CV6  4.7U_0603_6.3V6K  [C_0603]  65.04 67.52 270 top
CV7  22U_0603_6.3V6M  [C_0603]  59.87 61.65 270 top
CV8  22U_0603_6.3V6M  [C_0603]  61.21 61.65 270 top
CV9  22U_0603_6.3V6M  [C_0603]  58.54 61.65 270 top
CV10  22U_0603_6.3V6M  [C_0603]  56.95 60.44 0 bottom
CV11  0.22U_0402_16V7K  [C_0402]  68.16 59.34 90 bottom
CV12  0.22U_0402_16V7K  [C_0402]  67.26 59.34 90 bottom
CV13  0.22U_0402_16V7K  [C_0402]  65.43 59.33 90 bottom
CV14  0.22U_0402_16V7K  [C_0402]  66.32 59.33 90 bottom
CV15  0.22U_0402_16V7K  [C_0402]  64.54 59.33 90 bottom
CV16  0.22U_0402_16V7K  [C_0402]  63.66 59.33 90 bottom
CV17  0.22U_0402_16V7K  [C_0402]  62.77 59.33 90 bottom
CV18  0.22U_0402_16V7K  [C_0402]  61.88 59.33 90 bottom
CV19  0.1U_0201_10V6K  [C_0201]  70.68 65.12 270 top
CV20  0.1U_0201_10V6K  [C_0201]  64.73 69.4 0 top
CV21  10U_0603_6.3V6M  [C_0603]  65.21 61.65 270 top
CV22  1U_0402_6.3V6K  [C_0402]  66.99 67.59 180 top
CV23  1U_0402_6.3V6K  [C_0402]  62.76 68.49 270 top
CV24  10U_0603_6.3V6M  [C_0603]  63.87 61.65 270 top
CV25  10U_0603_6.3V6M  [C_0603]  66.54 61.65 270 top
CV26  1U_0402_6.3V6K  [C_0402]  55.05 63.77 0 top
CV27  1U_0402_6.3V6K  [C_0402]  57.74 63.77 180 top
CV28  10U_0603_6.3V6M  [C_0603]  53.14 60.44 180 bottom
CV29  1U_0402_6.3V6K  [C_0402]  64.56 68.54 0 top
CV30  10U_0603_6.3V6M  [C_0603]  71.13 71.9 180 top
CV31  0.1U_0402_10V7K  [C_0402]  72.24 75.01 0 top
CV32  22U_0603_6.3V6M  [C_0603]  72.25 73.95 0 top
CV34  0.1U_0402_10V7K  [C_0402]  70.63 75.46 180 top
CV35  22U_0603_6.3V6M  [C_0603]  71.13 73.11 180 top
CV36  15P_0402_50V8J  [C_0402]  76.59 92.7 180 bottom
CV37  15P_0402_50V8J  [C_0402]  77.51 92.7 0 bottom
CV38  4.7U_0603_6.3V6K  [C_0603]  60.51 76.06 270 top
CV39  0.1U_0201_10V6K  [C_0201]  54.03 76.32 270 top
CV40  4.7U_0603_6.3V6K  [C_0603]  52.65 86.25 0 top
CV41  1U_0402_6.3V6K  [C_0402]  54.73 80.26 270 top
CV42  1U_0402_6.3V6K  [C_0402]  53.9 84.33 270 top
CV43  0.1U_0201_10V6K  [C_0201]  54.6 76.32 270 top
CV44  10U_0603_6.3V6M  [C_0603]  64.83 79.11 0 top
CV45  22U_0603_6.3V6M  [C_0603]  59.81 71.87 90 top
CV46  0.1U_0201_10V6K  [C_0201]  67.06 79.68 270 top
CV47  1U_0402_6.3V6K  [C_0402]  67.83 79.85 270 top
CV48  4.7U_0603_6.3V6K  [C_0603]  72.95 79.98 90 top
CV49  1U_0402_6.3V6K  [C_0402]  71.88 80.07 90 top
CV50  0.1U_0201_10V6K  [C_0201]  70.68 80.24 90 top
CV51  22U_0603_6.3V6M  [C_0603]  59.55 70.48 270 top
CV52  0.1U_0402_10V7K  [C_0402]  56.73 79.26 0 top
CV53  0.1U_0402_10V7K  [C_0402]  63.54 80.98 0 top
CV54  4.7U_0603_6.3V6K  [C_0603]  67.11 81.14 90 top
CV55  0.1U_0402_10V7K  [C_0402]  59.46 74.43 180 top
CV56  0.1U_0402_25V6  [C_0402]  89.66 59.63 270 top
CV57  0.1U_0402_25V6  [C_0402]  88.27 83.43 180 top
CV58  1U_0402_6.3V6K  [C_0402]  91.64 59.62 180 top
CV59  0.1U_0402_25V6  [C_0402]  96.2 69.79 270 top
CV60  0.1U_0402_10V7K  [C_0402]  70.32 70.82 180 top
CV61  22U_0603_6.3V6M  [C_0603]  71.13 74.31 180 top
CV63  1U_0402_6.3V6K  [C_0402]  93.26 61.97 0 top
CV64  0.1U_0402_25V6  [C_0402]  90.35 68.65 270 top
CV65  0.1U_0402_25V6  [C_0402]  89.77 65.08 0 top
CV66  470P_0402_50V7K  [C_0402]  88.58 66.93 270 top
CV67  3300P_0402_50V7K  [C_0402]  88.14 62.35 180 top
CV69  0.1U_0201_10V6K  [C_0201]  70.11 80.24 90 top
CV70  0.01U_0402_25V7K  [C_0402]  75.48 102.61 0 bottom
CV71  0.01U_0402_25V7K  [C_0402]  48.77 100.38 180 bottom
CV72  0.1U_0201_10V6K  [C_0201]  34.41 96.28 90 top
CV73  0.1U_0201_10V6K  [C_0201]  36.59 91.61 135 top
CV74  0.1U_0201_10V6K  [C_0201]  48.19 91.6 270 top
CV75  0.1U_0201_10V6K  [C_0201]  38.83 102.73 180 top
CV76  0.1U_0201_10V6K  [C_0201]  48.63 94.2 270 top
CV77  0.1U_0201_10V6K  [C_0201]  39.81 93.43 90 top
CV78  0.1U_0201_10V6K  [C_0201]  42.13 102.61 180 top
CV79  0.1U_0201_10V6K  [C_0201]  38.45 95.62 180 top
CV80  0.1U_0201_10V6K  [C_0201]  46.7 98.67 180 top
CV81  0.1U_0201_10V6K  [C_0201]  45.37 101.59 180 top
CV82  0.1U_0201_10V6K  [C_0201]  40.51 90.31 90 top
CV83  470P_0402_50V7K  [C_0402]  88.14 61.46 180 top
CV105  0.01U_0402_25V7K  [C_0402]  31.95 78.29 180 top
CV106  0.01U_0402_25V7K  [C_0402]  31.95 70.92 180 top
CV117  1U_0402_6.3V6K  [C_0402]  98.11 68.25 180 top
CV162  1U_0402_6.3V6K  [C_0402]  63.18 92.84 270 top
CV163  10U_0603_6.3V6M  [C_0603]  75.43 100.58 0 top
CV164  0.1U_0201_10V6K  [C_0201]  63.44 94.54 180 top
CV165  0.1U_0201_10V6K  [C_0201]  63.44 94.54 180 bottom
CV166  1U_0402_6.3V6K  [C_0402]  75.42 97.02 0 top
CV167  1U_0402_6.3V6K  [C_0402]  75.42 97.02 0 bottom
CV168  1U_0402_6.3V6K  [C_0402]  75.42 97.91 0 bottom
CV169  10U_0603_6.3V6M  [C_0603]  62.1 92.83 270 bottom
CV170  10U_0603_6.3V6M  [C_0603]  75.43 100.64 0 bottom
CV198  0.1U_0201_10V6K  [C_0201]  63.44 93.78 180 top
CV199  0.1U_0201_10V6K  [C_0201]  75.33 99.62 0 top
CV200  0.1U_0402_10V7K  [C_0402]  83.88 73.22 180 top
CV201  0.1U_0201_10V6K  [C_0201]  63.44 93.78 180 bottom
CV202  0.1U_0201_10V6K  [C_0201]  75.33 99.62 0 bottom
CV203  10U_0603_6.3V6M  [C_0603]  75.49 101.85 0 top
CV204  1U_0402_6.3V6K  [C_0402]  75.42 97.91 0 top
CV205  1U_0402_6.3V6K  [C_0402]  75.42 98.8 0 top
CV206  1U_0402_6.3V6K  [C_0402]  75.42 98.8 0 bottom
CV207  1U_0402_6.3V6K  [C_0402]  63.18 92.84 270 bottom
CV235  0.1U_0201_10V6K  [C_0201]  48.93 96.89 180 bottom
CV236  1U_0402_6.3V6K  [C_0402]  48.77 103.37 180 bottom
CV237  1U_0402_6.3V6K  [C_0402]  48.77 99.43 180 bottom
CV238  10U_0603_6.3V6M  [C_0603]  48.76 104.51 180 bottom
CV239  0.1U_0201_10V6K  [C_0201]  48.93 96.26 180 bottom
CV240  0.1U_0201_10V6K  [C_0201]  60.76 94.52 270 bottom
CV241  1U_0402_6.3V6K  [C_0402]  48.77 98.54 180 bottom
CV242  1U_0402_6.3V6K  [C_0402]  48.77 97.65 180 bottom
CV243  10U_0603_6.3V6M  [C_0603]  48.76 105.78 180 bottom
CV244  10U_0603_6.3V6M  [C_0603]  48.57 103.75 270 top
CV245  10U_0603_6.3V6M  [C_0603]  48.57 104.83 90 top
CV246  0.1U_0201_10V6K  [C_0201]  48.93 96.26 180 top
CV247  0.1U_0201_10V6K  [C_0201]  48.93 96.89 180 top
CV248  1U_0402_6.3V6K  [C_0402]  48.77 97.65 180 top
CV249  1U_0402_6.3V6K  [C_0402]  48.77 98.54 180 top
CV250  0.1U_0201_10V6K  [C_0201]  48.93 95.5 180 top
CV251  1U_0402_6.3V6K  [C_0402]  48.77 99.43 180 top
CV252  1U_0402_6.3V6K  [C_0402]  48.77 100.38 180 top
CV253  0.1U_0201_10V6K  [C_0201]  31.97 81.4 180 top
CV254  1U_0402_6.3V6K  [C_0402]  31.95 83.18 180 top
CV255  1U_0402_6.3V6K  [C_0402]  31.95 82.22 180 top
CV256  10U_0603_6.3V6M  [C_0603]  31.74 86.61 90 top
CV257  0.1U_0201_10V6K  [C_0201]  43.87 77.37 270 top
CV258  0.1U_0201_10V6K  [C_0201]  44.95 77.37 270 top
CV259  1U_0402_6.3V6K  [C_0402]  49.09 80.9 270 top
CV260  1U_0402_6.3V6K  [C_0402]  45.76 77.21 0 top
CV261  10U_0603_6.3V6M  [C_0603]  31.74 85.59 270 top
CV262  1U_0402_6.3V6K  [C_0402]  39.87 62.81 270 top
CV263  0.1U_0201_10V6K  [C_0201]  43.81 62.77 270 top
CV264  1U_0402_6.3V6K  [C_0402]  40.89 62.81 270 top
CV265  10U_0603_6.3V6M  [C_0603]  35.36 62.6 180 top
CV266  0.1U_0201_10V6K  [C_0201]  44.51 62.77 270 top
CV267  0.1U_0201_10V6K  [C_0201]  45.27 62.77 270 top
CV268  1U_0402_6.3V6K  [C_0402]  41.9 62.81 270 top
CV269  1U_0402_6.3V6K  [C_0402]  42.92 62.81 270 top
CV270  10U_0603_6.3V6M  [C_0603]  36.38 62.6 0 top
CV271  10U_0603_6.3V6M  [C_0603]  31.74 86.61 90 bottom
CV272  10U_0603_6.3V6M  [C_0603]  31.74 85.59 270 bottom
CV273  0.1U_0201_10V6K  [C_0201]  31.97 81.4 180 bottom
CV274  0.1U_0201_10V6K  [C_0201]  44.95 77.37 270 bottom
CV275  1U_0402_6.3V6K  [C_0402]  31.95 82.22 180 bottom
CV276  1U_0402_6.3V6K  [C_0402]  31.95 83.18 180 bottom
CV277  0.1U_0201_10V6K  [C_0201]  43.87 77.37 270 bottom
CV278  1U_0402_6.3V6K  [C_0402]  45.76 77.21 0 bottom
CV279  1U_0402_6.3V6K  [C_0402]  36.06 89.34 0 bottom
CV280  10U_0603_6.3V6M  [C_0603]  37.01 62.6 0 bottom
CV281  10U_0603_6.3V6M  [C_0603]  40.82 62.6 180 bottom
CV282  0.1U_0201_10V6K  [C_0201]  45.27 62.77 270 bottom
CV283  0.1U_0201_10V6K  [C_0201]  45.84 74.76 90 bottom
CV284  1U_0402_6.3V6K  [C_0402]  41.9 62.81 270 bottom
CV285  1U_0402_6.3V6K  [C_0402]  42.92 62.81 270 bottom
CV286  0.1U_0201_10V6K  [C_0201]  45.21 74.76 90 bottom
CV287  1U_0402_6.3V6K  [C_0402]  44.13 62.81 270 bottom
CV288  1U_0402_6.3V6K  [C_0402]  46.65 74.86 0 bottom
CV289  10P_0402_50V8J  [C_0402]  91.64 58.67 180 top
CV290  10P_0402_50V8J  [C_0402]  98.11 67.3 180 top
CV291  10P_0402_50V8J  [C_0402]  88.7 59.63 270 top
CV292  10P_0402_50V8J  [C_0402]  88.27 82.54 180 top
CV293  10P_0402_50V8J  [C_0402]  93.26 61.08 0 top
CV295  10P_0402_50V8J  [C_0402]  89.46 68.65 270 top
CV296  10P_0402_50V8J  [C_0402]  89.77 64.19 0 top
CV297  10P_0402_50V8J  [C_0402]  117.35 92.57 180 top
CV298  10P_0402_50V8J  [C_0402]  117.35 94.86 180 top
CV299  10P_0402_50V8J  [C_0402]  134.98 91.37 0 top
CV300  10P_0402_50V8J  [C_0402]  134.98 90.48 0 top
CV301  10P_0402_50V8J  [C_0402]  94.35 90.35 90 top
CV302  10P_0402_50V8J  [C_0402]  92.44 95.75 0 bottom
CX1  0.1U_0402_10V7K  [C_0402]  4.93 86.67 0 top
CX2  0.1U_0402_10V7K  [C_0402]  6.13 88.7 90 top
CX3  10U_0805_10V6K  [C_0805]  7.42 88.48 90 top
CX4  0.1U_0402_10V7K  [C_0402]  2.34 90.36 270 top
CX5  0.1U_0603_25V7K  [C_0603]  2.28 78.38 270 top
CX6  1U_0603_25V7K  [C_0603]  5.77 74.98 180 top
CX7  4.7U_0805_10V4Z  [C_0805]  19.54 77.23 270 top
CX8  4.7U_0805_10V4Z  [C_0805]  8.92 87.43 0 top
CX9  0.1U_0402_10V7K  [C_0402]  10.27 92.45 0 top
CX11  0.1U_0402_10V7K  [C_0402]  8.95 88.75 90 top
CX12  0.1U_0402_10V7K  [C_0402]  195.59 82.94 180 bottom
CX13  0.1U_0402_10V7K  [C_0402]  195.59 83.82 180 bottom
CX14  0.1U_0402_10V7K  [C_0402]  195.52 79.56 180 bottom
CX15  0.1U_0402_10V7K  [C_0402]  195.52 80.45 180 bottom
CX16  0.1U_0402_10V7K  [C_0402]  195.46 86.49 180 bottom
CX17  0.1U_0402_10V7K  [C_0402]  195.46 87.38 180 bottom
CX18  0.1U_0402_10V7K  [C_0402]  195.59 89.83 180 bottom
CX19  0.1U_0402_10V7K  [C_0402]  195.59 90.72 180 bottom
CX21  0.1U_0402_16V7K  [C_0402]  199.76 81.07 90 top
CX22  10U_0603_6.3V6M  [C_0603]  198.56 80.76 90 top
CX49  4.7U_0805_10V4Z  [C_0805]  8.06 99.03 90 top
CX50  0.1U_0402_10V7K  [C_0402]  8.01 97.97 180 top
CX51  4.7U_0805_10V4Z  [C_0805]  12.76 99.15 90 top
DA8  -  [BAT54C-7-F_SOT23-3]  190.65 17.2 90 top
DA10  AZ5125-02S.R7G_SOT23-3  [AZ5125-02SPR7G_SOT23-3]  197.44 28.5 270 bottom
DA12  AZ5123-02S.R7G_SOT23-3  [AZ5123-02SPR7G_SOT23-3]  197.44 32.44 270 bottom
DA13  AZ5125-02S.R7G_SOT23-3  [AZ5125-02SPR7G_SOT23-3]  204.4 16.92 180 bottom
DA14  AZ5125-02S.R7G_SOT23-3  [AZ5125-02SPR7G_SOT23-3]  209.48 16.92 180 bottom
DB1  ACES_51522-01001-001  [ACES_51522-01001-001_10P]  128.3 18.89 180 bottom
DC1  -  [BAT54C-7-F_SOT23-3]  28.23 9.14 270 top
DC2  -  [RB751S40T1G_SOD523-2]  153.35 69.08 90 top
DC3  -  [RB751S40T1G_SOD523-2]  159.31 72.32 0 top
DC4  -  [RB751S40T1G_SOD523-2]  151.38 64.18 270 top
DC5  -  [RB751S40T1G_SOD523-2]  150.67 84.84 135 top
DC6  -  [RB751S40T1G_SOD523-2]  130.48 24.31 0 top
DC7  -  [RB751S40T1G_SOD523-2]  171.89 50.73 180 top
DC8  -  [RB551V-30_SOD323-2]  28.22 11.99 0 top
DE2  -  [L03ESDL5V0CC3-2_SOT23-3]  173.64 119.43 90 bottom
DE3  AZ5125-01H.R7G_SOD523-2  [AZ5125-01HPR7G_SOD523-2]  126.04 3.22 270 top
DE4  -  [RB551V-30_SOD323-2]  22.79 65.34 270 top
DI1  IP4292CZ10-TBR_XSON10_2.5X1~D  [IP4292CZ10-TBR_XSON10_2P5X1]  196.42 67.13 270 bottom
DI2  -  [L30ESDL5V0C3-2_SOT23-3]  195.47 63.41 0 bottom
DI3  S DIO(BR) TVWDF1004AD0 DFN ESD  [IP4292CZ10-TBR_XSON10_2P5X1]  15.5 75.58 0 top
DI4  IP4292CZ10-TBR_XSON10_2.5X1~D  [IP4292CZ10-TBR_XSON10_2P5X1]  196.69 48.43 270 bottom
DI5  -  [L30ESDL5V0C3-2_SOT23-3]  195.54 43.36 270 bottom
DM1  -  [RB551V-30_SOD323-2]  187.06 69.47 270 top
DV1  -  [RB751S40T1G_SOD523-2]  86.54 78.98 90 top
DX2  -  [PESD5V0U2BT_SOT23-3]  4.67 92.89 270 top
DX3  -  [RB551V-30_SOD323-2]  196.78 76.37 90 top
DX4  -  [BAW56W_SOT323-3]  196.97 72.98 180 bottom
DX5  -  [BAT54C-7-F_SOT23-3]  14.69 85.53 90 top
DX6  -  [BAT54C-7-F_SOT23-3]  8.29 81.53 270 top
DX7  -  [RB551V-30_SOD323-2]  150.48 23.3 0 top
DX8  -  [RB551V-30_SOD323-2]  158.1 3.74 0 top
DX9  -  [RB551V-30_SOD323-2]  14.48 91.56 180 top
FD1  FIDUCAL  [FIDUCIAL_C40M80]  210.37 2.85 180 bottom
FD2  FIDUCIAL  [FIDUCIAL_C40M80]  210.37 2.85 0 top
FD3  FIDUCAL  [FIDUCIAL_C40M80]  23.09 101.39 180 bottom
FD4  FIDUCIAL  [FIDUCIAL_C40M80]  12.5 105.91 0 top
FE1  0.5A_13.2V_NANOSMDC050F-13.2-2  [F_NANOSMDC050F-13P2-2]  117.76 22.66 180 top
FX1  1.5A_6V_1206L150PR~D  [F_1206L150PR]  198.76 79.31 270 top
FX2  1.1A_24V_SMD1812P110TF-24  [F_SMD1812P110TF-24]  14.74 96.57 180 top
FX3  SMD1812P150TF/24 1.5A UL/CSA/TUV  [F_SMD1812P110TF-24]  18.92 66.29 180 bottom
H1  -  [H_2P8N]  206.4 74.8 0 top
H2  -  [H_2P8]  198.4 118.8 0 top
H3  -  [H_2P8]  195.5 96.4 0 top
H4  -  [H_2P8]  183 32.1 90 top
H5  -  [H_2P8]  195 4 0 top
H6  -  [H_2P8]  101 3.5 0 top
H7  -  [H_2P8]  21.8 9.8 0 top
H8  -  [H_2P8-G]  82.8 57.8 0 top
H9  -  [H_2P8]  27.8 118.8 0 top
H11  -  [H_2P8]  22.1 92.1 0 top
H12  -  [H_2P8]  165.8 69.8 0 top
H13  -  [H_3P6-G]  165 105.4 0 top
H14  -  [H_3P6-G]  165 81.1 0 top
H15  -  [H_3P6-G]  101.81 105.42 0 top
H16  -  [H_3P6-G]  101.8 81.1 0 top
H17  -  [H_3P3-G]  83.45 93.35 0 top
H18  -  [H_3P3-G]  46.55 56.05 0 top
H19  -  [H_3P3]  181.73 91.35 0 top
H20  -  [H_2P8N]  195 10 0 top
H21  -  [H_2P8N]  204.4 118.8 0 top
H22  -  [H_2P8X3P3N]  34.04 118.85 90 top
H23  -  [H_2P8X4P8N]  208.31 22.28 90 top
HE1  100K_0402_1%_TSM0B104F4251RZ  [R_0402]  112.69 85.72 0 top
J510  -  [JUMP_43X79]  166.58 17.01 0 top
J511  -  [JUMP_43X79]  173.83 18.85 180 top
J521  -  [JUMP_43X39]  16.06 64.24 90 top
JC1  ACES_91960-0084N_MX25L3206EM2I  [ACES_91960-0084N_8P]  180.33 25.95 180 bottom
JCAM3D  STARC_111D10-000000-G4-R  [STARC_111D10-000000-G4-R_10P]  9.57 51.2 90 bottom
JDEG1  ACES_51522-01001-001  [ACES_51522-01001-001_10P]  121.66 5.17 90 bottom
JDIMM1  BELLW_80001-1021  [BELLW_80001-1021_204P]  96.15 47.7 180 bottom
JDIMM2  FOX_AS0A626-U4SN-7F  [FOX_AS0A626-U4SN-7F_204P]  108.55 34.74 0 bottom
JEDP  STARC_107K40-000001-G2  [STARC_107K40-000001-G2_40P]  1.76 99 270 bottom
JFAN  ACES_88231-03041  [ACES_88231-03041_3P]  7.05 72.04 180 bottom
JHDD  E&T_4260K-F10N-00L  [E-T_4260K-F10N-00L_10P]  180.73 12.52 180 bottom
JHDMI  CONCR_099ATAC19NBLCNF  [CONCR_099ATAC19NBLCNF_19P]  203.55 89.7 270 bottom
JHP  SINGA_2SJ3080-001111F  [SINGA_2SJ3080-001111F_6P]  201.74 36.91 90 bottom
JIO  ACES_51524-0160N-001  [ACES_51524-0160N-001_16P]  25.55 43.95 90 bottom
JKB  HB_A823020-SBHR21  [HB_A823020-SBHR21_30P]  91.75 47.75 270 top
JKBBL  ACES_50524-00401-P01  [ACES_50524-00401-P01_4P-T]  120.35 16.82 270 top
JLAN  J-L_TNBNRAC80015008  [SDAN_601028-008041_8P-T]  201.1 109.12 270 bottom
JLED  ACES_51524-0080N-001  [ACES_51524-0080N-001_8P]  12.75 58.3 270 top
JNGFF  LOTES_APCI0019-P009A  [LOTES_APCI0019-P009A_67P]  172.48 57.82 0 bottom
JP3  2MM  [JUMP_43X39]  188 95.18 0 top
JP13  -  [JUMP_43X79]  175.8 6.28 180 bottom
JP14  -  [JUMP_43X79]  170.51 43.68 0 top
JP15  -  [JUMP_43X79]  163.76 47.38 90 top
JP16  -  [JUMP_43X79]  173.45 96.96 180 top
JP17  -  [JUMP_43X79]  183.74 76.83 180 top
JP18  -  [JUMP_43X79]  173.45 93.08 180 top
JP19  -  [JUMP_43X79]  183.74 80.7 180 top
JRTC  ACES_50271-0020N-001  [ACES_50271-0020N-001_2P]  28.2 11.35 270 bottom
JSPK  ACES_50278-00401-001  [ACES_50278-00401-001_4P]  208.6 14.05 180 bottom
JTP  ACES_51524-0080N-001  [ACES_51524-0080N-001_8P]  20.66 60.25 0 top
JUSB1  TAITW_PUBAU6-09FLBS1NN4H0  [TAITW_PUBAU6-09FLBS1NN4H0_9P]  199.29 61.75 270 bottom
JUSB2  TAITW_PUBAU6-09FLBS1NN4H0  [TAITW_PUBAU6-09FLBS1NN4H0_9P]  199.29 43.55 270 bottom
JWDB1  CVILU_CI1804M1VRA-NH  [CVILU_CI1804M1VRA-NH_4P]  94.11 8.55 180 bottom
LA1  BLM15PX221SN1D_2P  [MURAT_BLM15PX221SN1D_2P]  199.95 14.53 270 bottom
LA3  BLM15PD800SN1D  [MURAT_BLM15BD601SN1D_2P]  210.5 18.66 270 top
LA4  BLM15PD800SN1D  [MURAT_BLM15BD601SN1D_2P]  208.46 18.66 270 top
LA5  BLM15PD800SN1D  [MURAT_BLM15BD601SN1D_2P]  205.42 18.66 270 top
LA6  BLM15PD800SN1D  [MURAT_BLM15BD601SN1D_2P]  203.38 18.66 270 top
LA7  BLM15PX330SN1D 0402  [MURAT_BLM15BD601SN1D_2P]  192.07 33.07 180 bottom
LA8  BLM15PD800SN1D  [MURAT_BLM15BD601SN1D_2P]  192.32 29.01 180 bottom
LA9  BLM15PD800SN1D  [MURAT_BLM15BD601SN1D_2P]  192.32 27.49 180 bottom
LA10  BLM15PX330SN1D 0402  [MURAT_BLM15BD601SN1D_2P]  192.07 31.55 180 bottom
LI2  MCM1012B900F06BP_4P  [INPAQ_MCM1012B900F06BP_4P]  195.01 58.86 0 bottom
LI5  MCM1012B900F06BP_4P  [INPAQ_MCM1012B900F06BP_4P]  189.8 43.56 0 bottom
LI8  MCM1012B900F06BP_4P  [INPAQ_MCM1012B900F06BP_4P]  30.21 54.72 180 bottom
LI9  S COM FI_ CHILISIN CMMI21T-670Y-N  [MURAT_DLW21SN670HQ2L_4P]  17.88 78.64 90 top
LI10  S COM FI_ CHILISIN CMMI21T-670Y-N  [MURAT_DLW21SN670HQ2L_4P]  15.98 80.74 90 top
LI11  MCM1012B900F06BP_4P  [INPAQ_MCM1012B900F06BP_4P]  30.21 57.71 180 bottom
LL1  2.2UH_LQM2MPN2R2NG0L_30%  [MURAT_LQM2MPN2R2NG0L_2P]  172.5 111.18 180 bottom
LV3  TDK MPZ1608S331AT _2P  [MURAT_BLM18PG331SN1D_2P]  72.49 70.17 180 top
LV4  MPZ1608S300AT_2P  [TDK_MPZ1608S300AT_2P]  60.78 70.56 270 top
LV5  MPZ1608S300AT_2P  [TDK_MPZ1608S300AT_2P]  72.46 71.41 90 top
LX1  0_0805_5%  [R0805_0OHM]  10.62 85.65 180 top
LX6  MCM1012B900F06BP_4P  [INPAQ_MCM1012B900F06BP_4P]  6.02 84.89 180 top
NOREF  -  []  34.85 -51.76 0 top
NOREF#2  -  []  93.72 63.28 0 top
NOREF#3  -  []  204.4 118.8 0 top
NOREF#4  -  []  181.73 91.35 0 top
NOREF#5  -  []  195.5 96.4 0 top
NOREF#6  -  []  101 3.5 0 top
NOREF#7  -  []  22.1 92.1 0 top
NOREF#8  -  []  165 105.4 0 top
NOREF#9  -  []  101.8 105.4 0 top
NOREF#10  -  []  195 4 0 top
NOREF#11  -  []  101.8 81.1 0 top
NOREF#12  -  []  183 32.1 0 top
NOREF#13  -  []  27.8 118.8 0 top
NOREF#14  -  []  136.92 84.27 0 top
NOREF#15  -  []  165 81.1 0 top
NOREF#16  -  []  21.8 9.8 0 top
NOREF#17  -  []  58.87 36.75 0 top
NOREF#18  -  []  55.3 8.18 0 top
NOREF#19  -  []  2.41 7.08 0 top
NOREF#20  -  []  165.8 69.8 0 top
NOREF#21  -  []  82.8 57.8 0 top
NOREF#22  -  []  45.59 36.06 270 top
NOREF#23  -  []  39.81 55.87 0 top
NOREF#24  -  []  101.53 51.87 0 top
NOREF#25  -  []  83.45 93.35 0 top
NOREF#26  -  []  46.55 56.05 0 top
NOREF#27  -  []  -25.66 169.47 0 top
NOREF#28  -  []  94.9 87.23 270 bottom
NOREF#29  -  []  129.96 103.05 270 bottom
NOREF#30  -  []  119.9 54.58 180 bottom
PBATT  LLTOP_ALLTOP C144LS-109A9-L 9P BATT P2  [ALLTO_C144LS-109A9-L_9P-T]  13.95 12.52 90 bottom
PC1  1000P_0402_50V7K  [C_0402]  16.58 104.8 270 top
PC2  0.1U_0402_25V7K  [C_0402]  17.53 104.8 270 top
PC3  1000P_0402_50V7K  [C_0402]  22.15 108.08 270 top
PC4  0.1U_0402_25V7K  [C_0402]  23.04 108.08 270 top
PC7  0.01U_0402_25V7K  [C_0402]  22.66 29.19 90 bottom
PC8  1000P_0402_50V7K  [C_0402]  17.9 29.38 90 bottom
PC14  .1U_0402_16V7K  [C_0402]  17.44 15.1 0 bottom
PC16  .1U_0402_16V7K  [C_0402]  36.51 114.69 270 top
PC100  0.1U_0402_25V6  [C_0402]  59.18 14.27 90 top
PC102  0.1U_0603_25V7K  [C_0603]  63.84 9.39 90 bottom
PC103  2200P_0402_50V7K  [C_0402]  57.21 13.89 90 bottom
PC104  10U_0805_25V6K  [C_0805]  58.54 13.55 90 bottom
PC105  10U_0805_25V6K  [C_0805]  60.57 11.89 270 bottom
PC106  22U_0805_6.3V6M  [C_0805]  77.41 15.04 90 bottom
PC107  22U_0805_6.3V6M  [C_0805]  74 15.04 90 bottom
PC108  22U_0805_6.3V6M  [C_0805]  75.7 15.04 90 bottom
PC109  22U_0805_6.3V6M  [C_0805]  71.88 15.99 90 bottom
PC110  22U_0805_6.3V6M  [C_0805]  75.18 10.6 270 bottom
